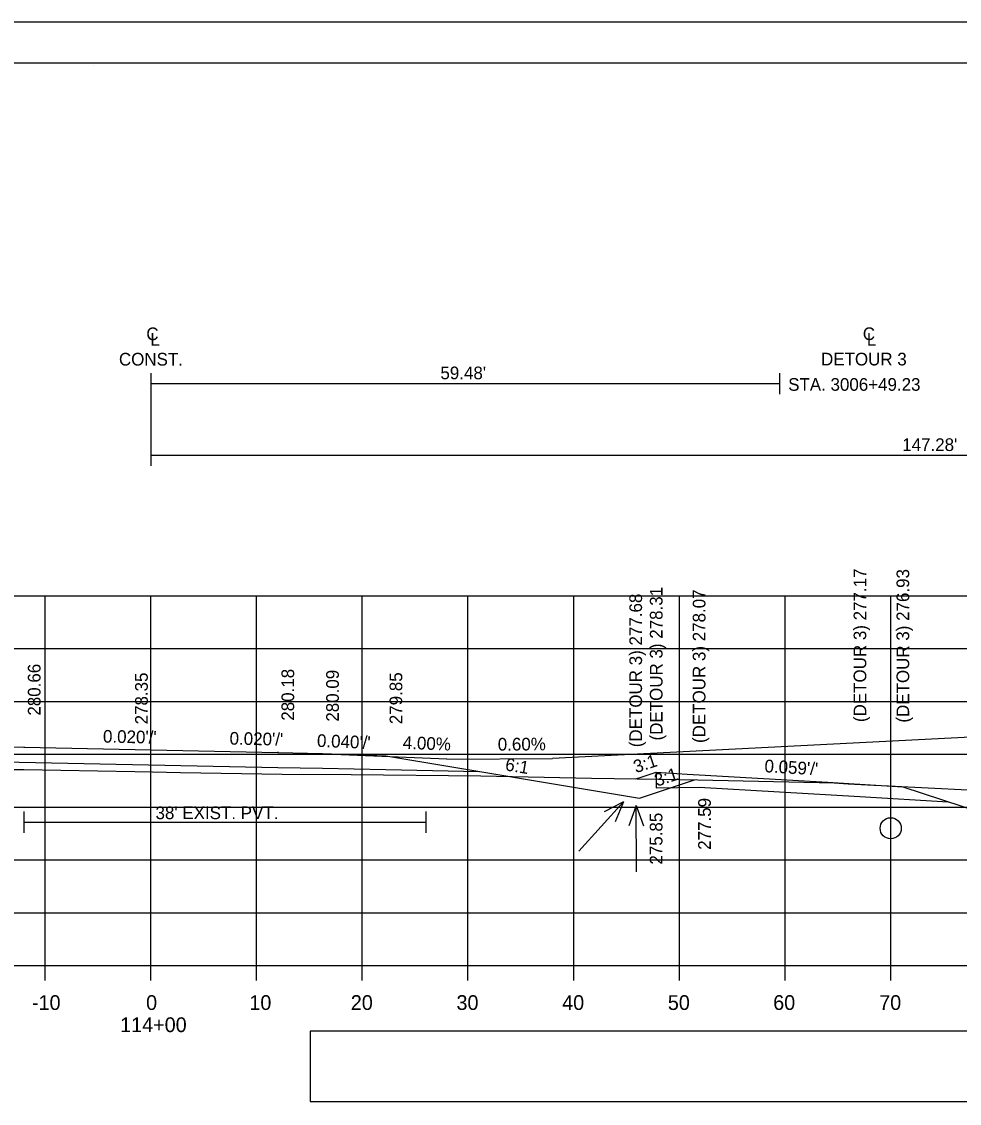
# Model space of a CAD drawing. Extents: x 285 to 4233, y -659 to 3710.
# Drawn here: x 527 to 615.8, y 513.8 to 616.2 of the extents above; entities that cross this region are included whole.
import ezdxf

# ---------------------------------------------------------------- set-up
doc = ezdxf.new("R2010")
doc.units = 0
for name, color, linetype in [('R_Alt Surface', 7, 'Continuous'), ('R_Axis', 7, 'Continuous'), ('R_Axis Annot', 7, 'Continuous'), ('R_Border', 7, 'Continuous'), ('R_Detour', 7, 'Continuous'), ('R_Drive', 7, 'Continuous'), ('R_Exist Surface', 7, 'Continuous'), ('R_Fin Surface', 7, 'Continuous'), ('R_Grid', 7, 'Continuous'), ('R_No Plot', 7, 'Continuous'), ('R_Proposed Const Limits', 7, 'Continuous'), ('R_Water', 7, 'Continuous'), ('R_Water Annot', 7, 'Continuous'), ('R_Xsect Elev', 7, 'Continuous'), ('R_Xsect Slope', 7, 'Continuous')]:
    doc.layers.add(name, color=color, linetype=linetype)

msp = doc.modelspace()

# ---------------------------------------------------------------- linework, layer by layer
at = {"layer": 'R_Alt Surface'}
for points in [[(539.28, 582.92), (539.28, 578.68)], [(598.76, 582.92), (598.76, 580.92)], [(539.28, 581.92), (598.76, 581.92)], [(539.28, 578.68), (539.28, 574.13)], [(539.28, 575.13), (686.56, 575.13)], [(505.44, 545.71), (517.28, 545.95), (525.28, 546.11), (551.28, 545.59), (555.51, 545.51), (561.51, 545.39), (570.35, 545.21)], [(527.24, 541.4), (527.24, 539.4)], [(565.28, 541.4), (565.28, 539.4)], [(527.24, 540.4), (565.28, 540.4)]]:
    msp.add_lwpolyline(points, dxfattribs=at)
at = {"layer": 'R_Axis'}
for p, q in [((389.28, 526.83), (689.28, 526.83)), ((529.28, 525.43), (529.28, 526.83)), ((539.28, 525.43), (539.28, 526.83)), ((549.28, 525.43), (549.28, 526.83)), ((559.28, 525.43), (559.28, 526.83)), ((569.28, 525.43), (569.28, 526.83)), ((579.28, 525.43), (579.28, 526.83)), ((589.28, 525.43), (589.28, 526.83)), ((599.28, 525.43), (599.28, 526.83)), ((609.28, 525.43), (609.28, 526.83))]:
    msp.add_line(p, q, dxfattribs=at)
at = {"layer": 'R_Axis Annot'}
msp.add_lwpolyline([(554.36, 513.98), (694.72, 513.98), (694.72, 520.63), (554.36, 520.63)], close=True, dxfattribs=at)
at = {"layer": 'R_Border'}
for p, q in [((381.28, 612.29), (697.46, 612.29)), ((533.8, 612.03), (533.8, 612.03)), ((533.8, 612.03), (533.8, 612.03))]:
    msp.add_line(p, q, dxfattribs=at)
at = {"layer": 'R_Detour'}
msp.add_line((587.09, 545.14), (587.08, 543.66), dxfattribs=at)
for points in [[(585.15, 544.5), (585.68, 544.68), (587.09, 545.14), (590.03, 544.96), (591.15, 544.9), (603.32, 544.18), (605.33, 544.06), (606.37, 544), (606.85, 543.97), (610.43, 543.76), (617.95, 541.28), (625.42, 538.81), (627.3, 539.43), (632.33, 541.08), (634.42, 541.77), (637.44, 542.76)], [(587.08, 543.66), (591.15, 543.73), (606.37, 542.83), (614.73, 542.34)]]:
    msp.add_lwpolyline(points, dxfattribs=at)
at = {"layer": 'R_Drive'}
for p, q in [((689.28, 552.16), (577.27, 546.43)), ((567.27, 546.37), (557.28, 546.77)), ((567.27, 546.37), (577.27, 546.43))]:
    msp.add_line(p, q, dxfattribs=at)
at = {"layer": 'R_Exist Surface'}
msp.add_lwpolyline([(524.38, 545.4), (527.24, 545.4), (537.75, 545.21), (539.43, 545.17), (542.06, 545.12), (551.7, 544.94), (558.21, 544.92), (570.48, 544.78), (580.96, 544.57), (587.43, 544.47), (591.02, 544.41), (603.93, 544.12), (605.27, 544.03), (607.69, 543.9), (609.07, 543.83), (620.33, 543.29)], dxfattribs=at)
at = {"layer": 'R_Fin Surface'}
msp.add_lwpolyline([(465.81, 544.65), (482, 539.26), (497.28, 544.35), (517.28, 547.69), (525.28, 547.53), (527.28, 547.49), (551.28, 547.01), (555.51, 546.92), (561.51, 546.68), (585.51, 542.68), (590.71, 544.42)], dxfattribs=at)
at = {"layer": 'R_Grid'}
for p, q in [((389.28, 561.83), (689.28, 561.83)), ((529.28, 526.83), (529.28, 561.83)), ((539.28, 526.83), (539.28, 561.83)), ((549.28, 526.83), (549.28, 561.83)), ((559.28, 526.83), (559.28, 561.83)), ((569.28, 526.83), (569.28, 561.83)), ((579.28, 526.83), (579.28, 561.83)), ((589.28, 526.83), (589.28, 561.83)), ((599.28, 526.83), (599.28, 561.83)), ((609.28, 526.83), (609.28, 561.83)), ((389.28, 556.83), (689.28, 556.83)), ((389.28, 551.83), (689.28, 551.83)), ((389.28, 546.83), (689.28, 546.83)), ((389.28, 541.83), (689.28, 541.83)), ((389.28, 536.83), (689.28, 536.83)), ((389.28, 531.83), (689.28, 531.83)), ((389.28, 526.83), (689.28, 526.83))]:
    msp.add_line(p, q, dxfattribs=at)
at = {"layer": 'R_No Plot'}
msp.add_line((368.88, 616.18), (702.21, 616.18), dxfattribs=at)
for points in [[(368.87, 616.18), (702.21, 616.18), (702.21, 402.85), (368.87, 402.85)], [(615.2, 612.29), (634.82, 612.29), (634.82, 602.41), (650.93, 602.41), (674.13, 602.41), (674.25, 574.25), (697.46, 574.25), (697.46, 406.83), (381.28, 406.83), (381.28, 612.29)]]:
    msp.add_lwpolyline(points, close=True, dxfattribs=at)
at = {"layer": 'R_Proposed Const Limits'}
for points in [[(527.28, 547.54), (527.28, 547.51), (527.28, 547.5), (527.28, 547.49), (527.28, 547.46), (527.28, 547.46), (527.28, 547.44)], [(551.28, 547.06), (551.28, 547.03), (551.28, 547.02), (551.28, 547.01), (551.28, 546.98), (551.28, 546.98), (551.28, 546.96)]]:
    msp.add_lwpolyline(points, dxfattribs=at)
at = {"layer": 'R_Water'}
msp.add_circle((609.28, 539.83), 1, dxfattribs=at)
at = {"layer": 'R_Water Annot'}
for p, q in [((579.78, 537.65), (583.98, 542.33)), ((583.98, 542.33), (582.17, 541.37)), ((583.98, 542.33), (583.21, 540.43)), ((585.19, 541.99), (584.5, 540.07)), ((585.21, 535.71), (585.19, 541.99)), ((585.19, 541.99), (585.9, 540.07))]:
    msp.add_line(p, q, dxfattribs=at)
at = {"layer": 'R_Xsect Elev'}
msp.add_line((539.28, 545.18), (539.28, 555.18), dxfattribs=at)

# ---------------------------------------------------------------- texts
at = {"layer": 'R_Alt Surface'}
for s, height, p in [('C', 1.2, (538.84, 586.03)), ('C', 1.2, (606.64, 586.04)), ('L', 1.2, (539.23, 585.5)), ('L', 1.2, (607.02, 585.51)), ('CONST.', 1.199, (536.25, 583.63)), ('DETOUR 3', 1.199, (602.69, 583.64)), ('STA. 3006+49.23', 1.1985, (599.58, 581.24))]:
    msp.add_text(s, height=height, dxfattribs=at).set_placement(p)
at = {"layer": 'R_Axis Annot'}
for s, p in [('-10', (528.02, 522.63)), ('0', (538.82, 522.63)), ('10', (548.59, 522.63)), ('20', (558.19, 522.63)), ('30', (568.19, 522.63)), ('40', (578.19, 522.63)), ('50', (588.19, 522.63)), ('60', (598.16, 522.63)), ('70', (608.19, 522.63)), ('114+00', (536.36, 520.53))]:
    msp.add_text(s, height=1.4, dxfattribs=at).set_placement(p)
at = {"layer": 'R_Water'}
for s, p in [("59.48'", (566.67, 582.33)), ("147.28'", (610.37, 575.54)), ("38' EXIST. PVT.", (539.71, 540.69))]:
    msp.add_text(s, height=1.2, dxfattribs=at).set_placement(p)
at = {"layer": 'R_Xsect Elev'}
for s, rotation, p in [('(DETOUR 3) 277.17', 90, (606.97, 549.88)), ('(DETOUR 3) 276.93', 90, (611.03, 549.83)), ('(DETOUR 3) 278.31', 90, (587.69, 548.14)), ('(DETOUR 3) 278.07', 90, (591.75, 547.9)), ('(DETOUR 3) 277.68', 90, (585.75, 547.5)), ('280.66', 90, (528.83, 550.49)), ('278.35', 90, (538.98, 549.66)), ('280.18', 90, (552.83, 550.01)), ('280.09', 90, (557.06, 549.92)), ('279.85', 90, (563.06, 549.68)), ('4.00%', 357.71, (563.09, 547.36)), ('0.60%', 0.3438, (572.1, 547.18)), ('277.59', 90, (592.26, 537.79)), ('275.85', 90, (587.68, 536.39))]:
    msp.add_text(s, height=1.2, rotation=rotation, dxfattribs=at).set_placement(p)
at = {"layer": 'R_Xsect Slope'}
for s, rotation, p in [("0.020'/'", 358.8542, (534.73, 547.94)), ("0.020'/'", 358.8542, (546.71, 547.75)), ("0.040'/'", 357.7094, (554.97, 547.54)), ('6:1', 350.5377, (572.74, 545.32)), ('3:1', 18.0967, (585.17, 545.04)), ("0.059'/'", 356.6257, (597.31, 545.14)), ('3:1', 18.4349, (587.16, 543.76))]:
    msp.add_text(s, height=1.2, rotation=rotation, dxfattribs=at).set_placement(p)

doc.saveas('drawing.dxf')
